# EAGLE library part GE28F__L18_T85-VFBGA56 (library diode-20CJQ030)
Intel StrataFlash® Wireless Memory (L18) 28F640L18, 28F128L18, 28F256L18 Package: VFBGA-56 Description: The Intel StrataFlash® wireless memory (L18) device is the latest generation of Intel StrataFlash® memory devices featuring flexible, multiple-partition, dual operation. It provides high performance synchronous-burst read mode and asynchronous read mode using 1.8 V lowvoltage, multi-level cell (MLC) technology. High performance Read-While-Write/Erase -85 ns initial access -54 MHz with zero wait state, 14 ns clock-todata output synchronous-burst mode -25 ns asynchronous-page mode -4-, 8-, 16-, and continuous-word burst mode -Burst suspend -Programmable WAIT configuration -Buffered Enhanced Factory Programming (Buffered EFP): 5 µs/byte (Typ) -1.8 V low-power buffered and non-buffered programming at 7 µs/byte (Typ) Architecture -Asymmetrically-blocked architecture -Multiple 8-Mbit partitions: 64Mb and 128Mb devices -Multiple 16-Mbit partitions: 256Mb devices -Four 16-Kword parameter blocks: top or bottom configurations -64-Kword main blocks -Dual-operation: Read-While-Write (RWW) or Read-While-Erase (RWE) -Status register for partition and device status Power -1.7 V - 2.0 V VCC operation -I/O voltage: 1.35 V - 2.0 V, 1.7 V - 2.0 V -Standby current: 25 µA (Typ) -4-Word synchronous read current: 17 mA (Typ) at 54 MHz -Automatic Power Savings (APS) mode Please send any comments to: messi@users.sourceforge.net
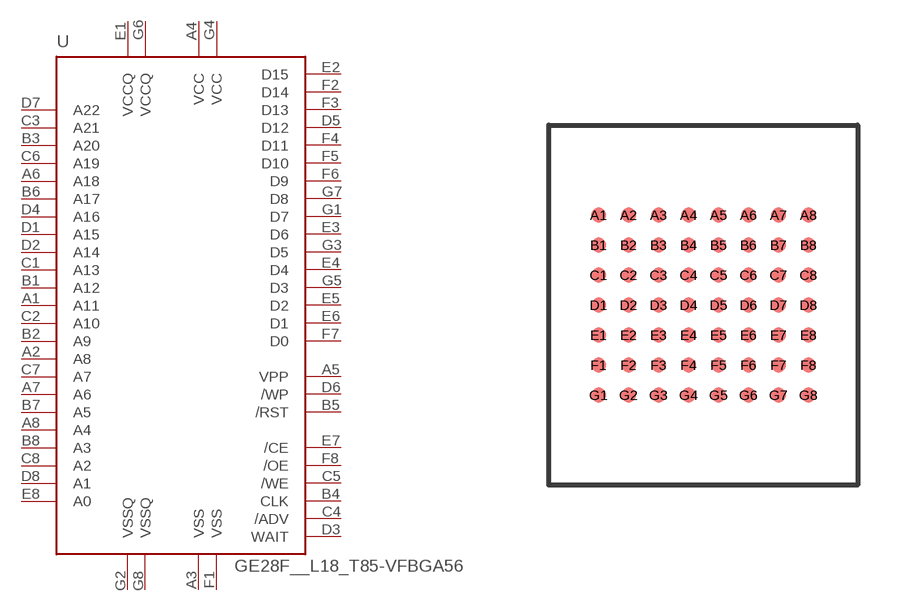
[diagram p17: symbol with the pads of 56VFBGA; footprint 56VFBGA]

Designator prefix U

## GE28F__L18_T85-VFBGA56  [56VFBGA]
A1  A11  in
A2  A8  in
A3  VSS  pwr
A4  VCC  in
A5  VPP  pwr
A6  A18  in
A7  A6  in
A8  A4  in
B1  A12  in
B2  A9  in
B3  A20  in
B4  CLK  in
B5  /RST  in
B6  A17  in
B7  A5  in
B8  A3  in
C1  A13  in
C2  A10  in
C3  A21  in
C4  /ADV  in
C5  /WE  in
C6  A19  in
C7  A7  in
C8  A2  in
D1  A15  in
D2  A14  in
D3  WAIT  out
D4  A16  in
D5  D12
D6  /WP  in
D7  A22  in
D8  A1  in
E1  VCCQ  in
E2  D15
E3  D6
E4  D4
E5  D2
E6  D1
E7  /CE  in
E8  A0  in
F1  VSS  pwr
F2  D14
F3  D13
F4  D11
F5  D10
F6  D9
F7  D0
F8  /OE  in
G1  D7
G2  VSSQ  pwr
G3  D5
G4  VCC  in
G5  D3
G6  VCCQ  in
G7  D8
G8  VSSQ  pwr

## Footprint 56VFBGA (pad centres in mm)
64- and 128-Mbit, 56-Ball VF BGA Package package with a 7 x 8 active-ball matrix pitch: 0.75 mm balldiameter: 0.375 Please send any comments to: messi@users.sourceforge.net
smd 0.375 x 0.375: A1 -2.625,2.25; A2 -1.875,2.25; A3 -1.125,2.25; A4 -0.375,2.25; A5 0.375,2.25; A6 1.125,2.25; A7 1.875,2.25; A8 2.625,2.25; B1 -2.625,1.5; B2 -1.875,1.5; B3 -1.125,1.5; B4 -0.375,1.5; B5 0.375,1.5; B6 1.125,1.5; B7 1.875,1.5; B8 2.625,1.5; C1 -2.625,0.75; C2 -1.875,0.75; C3 -1.125,0.75; C4 -0.375,0.75; C5 0.375,0.75; C6 1.125,0.75; C7 1.875,0.75; C8 2.625,0.75; D1 -2.625,0; D2 -1.875,0; D3 -1.125,0; D4 -0.375,0; D5 0.375,0; D6 1.125,0; D7 1.875,0; D8 2.625,0; E1 -2.625,-0.75; E2 -1.875,-0.75; E3 -1.125,-0.75; E4 -0.375,-0.75; E5 0.375,-0.75; E6 1.125,-0.75; E7 1.875,-0.75; E8 2.625,-0.75; F1 -2.625,-1.5; F2 -1.875,-1.5; F3 -1.125,-1.5; F4 -0.375,-1.5; F5 0.375,-1.5; F6 1.125,-1.5; F7 1.875,-1.5; F8 2.625,-1.5; G1 -2.625,-2.25; G2 -1.875,-2.25; G3 -1.125,-2.25; G4 -0.375,-2.25; G5 0.375,-2.25; G6 1.125,-2.25; G7 1.875,-2.25; G8 2.625,-2.25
